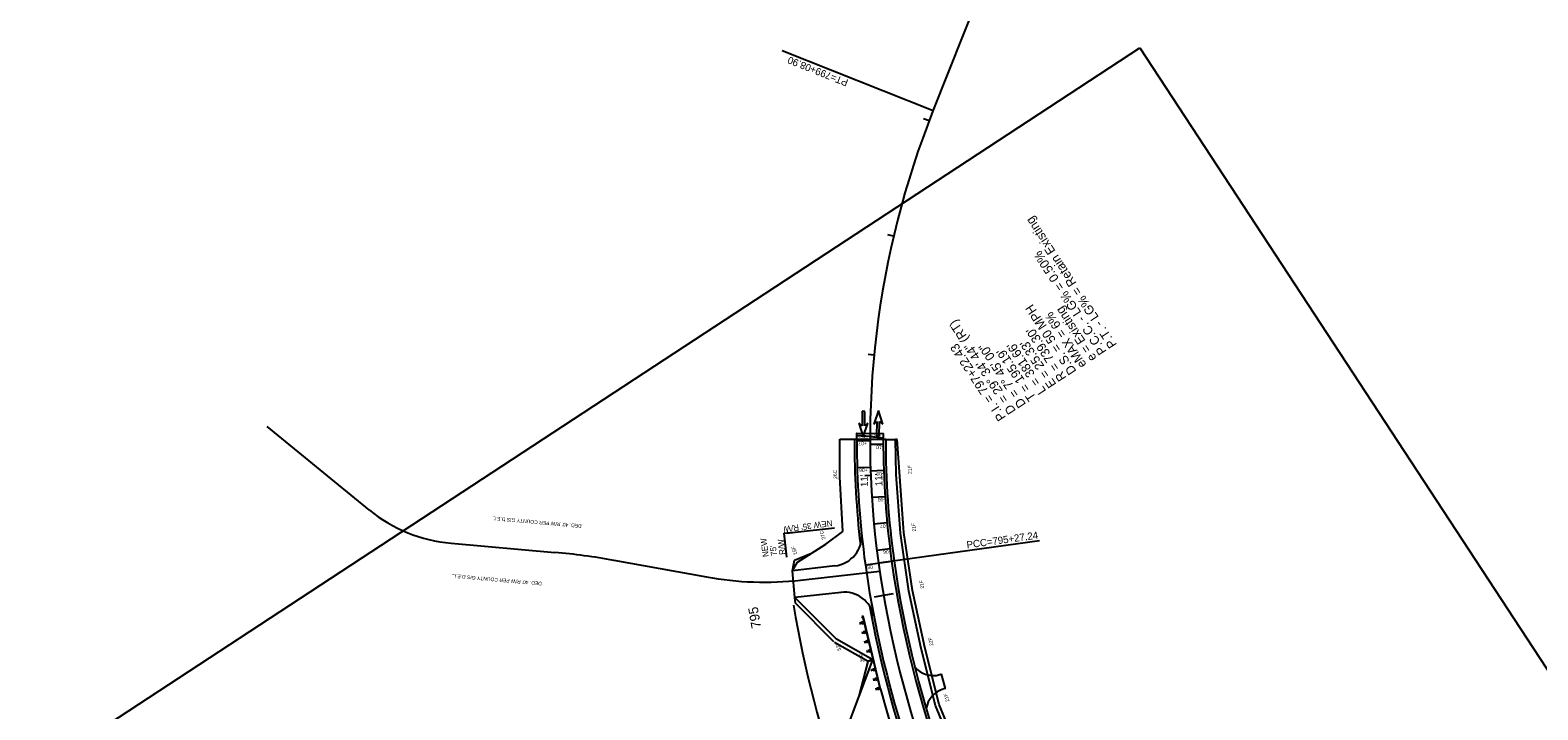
# Model space of a CAD drawing. Extents: x 1551641 to 1624343, y 1119533 to 1136600.
# Drawn here: x 1551641 to 1552891, y 1134769 to 1135333 of the extents above; entities that cross this region are included whole.
import ezdxf

# ---------------------------------------------------------------- set-up
doc = ezdxf.new("R2010")
doc.units = 0
for name, color, linetype in [('Prop CMT Pvmt Surface', 7, 'Continuous'), ('Prop CMT Pvmt Wedge Surface 1', 7, 'Continuous'), ('RD_HC_Cl', 7, 'Continuous'), ('RD_HC_Data', 7, 'Continuous'), ('RD_HC_Data_Tic', 7, 'Continuous'), ('RD_HC_TX_Sta50', 7, 'Continuous'), ('RD_PD_CstnLmt_TX', 7, 'Continuous'), ('RD_Sketch1', 7, 'Continuous'), ('RD_TX_Pipe_ElevEX', 7, 'Continuous'), ('RD_XS_Base', 7, 'Continuous'), ('RD_XS_EarthShd', 7, 'Continuous'), ('RD_XS_ExPaveRet', 7, 'Continuous'), ('RD_XS_Pave', 7, 'Continuous'), ('RD_XS_PaveOvlay', 7, 'Continuous'), ('RD_XS_PaveShd', 7, 'Continuous'), ('RD_XS_TX_Elev_EX', 7, 'Continuous'), ('RD_XS_TX_Slope', 7, 'Continuous'), ('Scratch_Level_0', 7, 'Continuous')]:
    doc.layers.add(name, color=color, linetype=linetype)

msp = doc.modelspace()

# ---------------------------------------------------------------- linework, layer by layer
at = {"layer": 'Prop CMT Pvmt Surface'}
for p, q in [((1552326, 1134992.4), (1552337, 1134992.4)), ((1552337, 1134989.4), (1552348, 1134989.5)), ((1552326.4, 1134970.1), (1552337.4, 1134970.4)), ((1552337.5, 1134967.5), (1552348.5, 1134967.8)), ((1552338.6, 1134945.5), (1552349.5, 1134946.2)), ((1552340.3, 1134923.5), (1552351.2, 1134924.6)), ((1552342.7, 1134901.7), (1552353.6, 1134903)), ((1552333.2, 1134889.5), (1552355, 1134892.5))]:
    msp.add_line(p, q, dxfattribs=at)
at = {"layer": 'Prop CMT Pvmt Wedge Surface 1'}
for p, q in [((1551640.7, 1134715.1), (1552560.8, 1135318)), ((1552560.8, 1135318), (1553547.3, 1133812.4))]:
    msp.add_line(p, q, dxfattribs=at)
at = {"layer": 'RD_HC_Cl'}
for p, q in [((1552389.3, 1135265.7), (1552583.4, 1135754.6)), ((1551836.8, 1135004), (1551921.8, 1134934.9)), ((1551989.6, 1134907.4), (1552075.6, 1134899.8)), ((1552124.5, 1134893.2), (1552201.5, 1134879.4)), ((1552279.4, 1134876.7), (1552345.1, 1134884.1))]:
    msp.add_line(p, q, dxfattribs=at)
for centre, radius, start, end in [((1553076.3, 1134992.8), 739.3, 158.3369, 187.9158), ((1552000.7, 1135031.9), 125, 230.9163, 264.9331), ((1552027, 1134351.9), 550, 79.7884, 84.9331), ((1552249.4, 1135145.1), 270, 259.7884, 276.3798)]:
    msp.add_arc(centre, radius, start, end, dxfattribs=at)
at = {"layer": 'RD_HC_Data'}
for p, q in [((1552389.3, 1135265.7), (1552264.1, 1135315.5)), ((1552344.1, 1134891), (1552477.5, 1134909.6))]:
    msp.add_line(p, q, dxfattribs=at)
at = {"layer": 'RD_HC_Data_Tic'}
for p, q in [((1552386, 1135257.4), (1552381.3, 1135259.2)), ((1552356.6, 1135161.9), (1552351.8, 1135163.1)), ((1552340.4, 1135063.3), (1552335.4, 1135063.8)), ((1552337.6, 1134963.5), (1552332.6, 1134963.3)), ((1552348.3, 1134864.1), (1552340.4, 1134862.7)), ((1552356.2, 1134865.5), (1552348.3, 1134864.1))]:
    msp.add_line(p, q, dxfattribs=at)
at = {"layer": 'RD_Sketch1'}
for p, q in [((1552324, 1134993.5), (1552326, 1134993.5)), ((1552350, 1134993.4), (1552348, 1134993.4))]:
    msp.add_line(p, q, dxfattribs=at)
for centre, radius, start, end in [((1553076.3, 1134992.8), 752.3, 179.952, 186.6169), ((1553076.3, 1134992.8), 726.3, 179.952, 187.9158), ((1553169.1, 1135005.7), 820, 187.9158, 213.2337), ((1553169.1, 1135005.7), 846, 190.2195, 209.0605)]:
    msp.add_arc(centre, radius, start, end, dxfattribs=at)
at = {"layer": 'RD_TX_Pipe_ElevEX'}
for q in [(1552326, 1134996.7), (1552348, 1134994.8)]:
    msp.add_line((1552337, 1134995.9), q, dxfattribs=at)
msp.add_lwpolyline([(1552326, 1134993.5), (1552326, 1134998.5), (1552348, 1134998.4), (1552348, 1134993.4)], close=True, dxfattribs=at)
msp.add_lwpolyline([(1552326, 1134996.7), (1552329.6, 1134996.4), (1552336.1, 1134996), (1552336.6, 1134996), (1552348, 1134994.8)], dxfattribs=at)
at = {"layer": 'RD_XS_Base'}
for p, q in [((1552331.3, 1134846.8), (1552330.3, 1134846.5)), ((1552330.3, 1134846.5), (1552330.5, 1134845.6)), ((1552345.8, 1134786.5), (1552331.3, 1134846.8)), ((1552328.6, 1134841.8), (1552329, 1134840.1)), ((1552330.1, 1134841.2), (1552328.8, 1134840.9)), ((1552329.9, 1134842.1), (1552331.8, 1134842.5)), ((1552330.3, 1134840.4), (1552329.9, 1134842.1)), ((1552332.2, 1134840.8), (1552330.3, 1134840.4)), ((1552330.5, 1134845.6), (1552331, 1134845.7)), ((1552330.5, 1134834), (1552330.9, 1134832.3)), ((1552331.9, 1134833.4), (1552330.7, 1134833.1)), ((1552331, 1134845.7), (1552345.3, 1134786.4)), ((1552331.7, 1134834.3), (1552333.7, 1134834.8)), ((1552332.1, 1134832.6), (1552331.7, 1134834.3)), ((1552331.8, 1134842.5), (1552332.2, 1134840.8)), ((1552333.7, 1134834.8), (1552334.1, 1134833.1)), ((1552334.1, 1134833.1), (1552332.1, 1134832.6)), ((1552332.4, 1134826.2), (1552332.8, 1134824.5)), ((1552333.8, 1134825.7), (1552332.6, 1134825.4)), ((1552333.6, 1134826.5), (1552335.5, 1134827)), ((1552334, 1134824.8), (1552333.6, 1134826.5)), ((1552336, 1134825.3), (1552334, 1134824.8)), ((1552335.5, 1134827), (1552336, 1134825.3)), ((1552334.3, 1134818.4), (1552334.7, 1134816.7)), ((1552335.7, 1134817.9), (1552334.5, 1134817.6)), ((1552335.5, 1134818.7), (1552337.4, 1134819.2)), ((1552335.9, 1134817), (1552335.5, 1134818.7)), ((1552337.8, 1134817.5), (1552335.9, 1134817)), ((1552336.1, 1134810.7), (1552336.6, 1134809)), ((1552337.6, 1134810.1), (1552336.3, 1134809.8)), ((1552337.4, 1134819.2), (1552337.8, 1134817.5)), ((1552337.4, 1134811), (1552339.3, 1134811.4)), ((1552337.8, 1134809.3), (1552337.4, 1134811)), ((1552339.7, 1134809.7), (1552337.8, 1134809.3)), ((1552339.3, 1134811.4), (1552339.7, 1134809.7)), ((1552338, 1134802.9), (1552338.4, 1134801.2)), ((1552339.4, 1134802.3), (1552338.2, 1134802)), ((1552339.2, 1134803.2), (1552341.2, 1134803.6)), ((1552339.6, 1134801.5), (1552339.2, 1134803.2)), ((1552341.6, 1134801.9), (1552339.6, 1134801.5)), ((1552341.2, 1134803.6), (1552341.6, 1134801.9)), ((1552339.9, 1134795.1), (1552340.3, 1134793.4)), ((1552341.3, 1134794.5), (1552340.1, 1134794.3)), ((1552341.1, 1134795.4), (1552343.1, 1134795.9)), ((1552341.5, 1134793.7), (1552341.1, 1134795.4)), ((1552343.5, 1134794.2), (1552341.5, 1134793.7)), ((1552341.8, 1134787.3), (1552342.2, 1134785.6)), ((1552343.2, 1134786.8), (1552342, 1134786.5)), ((1552343, 1134787.6), (1552344.9, 1134788.1)), ((1552343.4, 1134785.9), (1552343, 1134787.6)), ((1552343.1, 1134795.9), (1552343.5, 1134794.2)), ((1552345.3, 1134786.4), (1552343.4, 1134785.9)), ((1552344.9, 1134788.1), (1552345.3, 1134786.4)), ((1552345.3, 1134786.4), (1552345.8, 1134786.5))]:
    msp.add_line(p, q, dxfattribs=at)
msp.add_arc((1553169.1, 1135005.7), 852, 194.9094, 208.1262, dxfattribs=at)
at = {"layer": 'RD_XS_EarthShd'}
msp.add_line((1552326, 1134993.5), (1552348, 1134993.4), dxfattribs=at)
for centre, radius, start, end in [((1553076.3, 1134992.8), 750.3, 179.952, 187.9158), ((1553076.3, 1134992.8), 728.3, 179.952, 187.9158), ((1553169.1, 1135005.7), 844, 187.9158, 213.2337), ((1553169.1, 1135005.7), 822, 187.9158, 213.2337)]:
    msp.add_arc(centre, radius, start, end, dxfattribs=at)
at = {"layer": 'RD_XS_ExPaveRet'}
for p, q in [((1552359.5, 1134993.4), (1552358, 1134993.4)), ((1552365.1, 1134916.2), (1552359.5, 1134993.4)), ((1552372.1, 1134868.2), (1552365.1, 1134916.2)), ((1552274.3, 1134893.2), (1552288.6, 1134899.2)), ((1552272.8, 1134884.6), (1552274.3, 1134893.2)), ((1552275.2, 1134857.7), (1552274.8, 1134862.4)), ((1552382.4, 1134820.8), (1552372.1, 1134868.2)), ((1552307, 1134825.7), (1552275.2, 1134857.7)), ((1552335.5, 1134809.3), (1552307.6, 1134825.2)), ((1552327.9, 1134780.6), (1552335.5, 1134809.3)), ((1552394.2, 1134773.8), (1552382.4, 1134820.8)), ((1552412.8, 1134729), (1552394.2, 1134773.8))]:
    msp.add_line(p, q, dxfattribs=at)
at = {"layer": 'RD_XS_Pave'}
msp.add_line((1552274.9, 1134916.5), (1552307.5, 1134920.1), dxfattribs=at)
for centre, radius, start, end in [((1552249.4, 1135145.1), 230, 274.0673, 276.3798), ((1553076.3, 1134992.8), 814.3, 185.4382, 186.8463), ((1553169.1, 1135005.7), 908, 189.4862, 209.8315)]:
    msp.add_arc(centre, radius, start, end, dxfattribs=at)
at = {"layer": 'RD_XS_PaveOvlay'}
for p, q in [((1552330.6, 1135016.8), (1552330.4, 1135004.8)), ((1552332.8, 1135016.7), (1552330.6, 1135016.8)), ((1552332.6, 1135004.7), (1552332.8, 1135016.7)), ((1552344, 1135017.4), (1552340.1, 1135006.2)), ((1552347.5, 1135006), (1552344, 1135017.4)), ((1552327.8, 1135006.9), (1552331.3, 1134995.6)), ((1552330.4, 1135004.8), (1552327.8, 1135006.9)), ((1552331.3, 1134995.6), (1552335.2, 1135006.8)), ((1552335.2, 1135006.8), (1552332.6, 1135004.7)), ((1552340.1, 1135006.2), (1552342.7, 1135008.2)), ((1552342.7, 1135008.2), (1552342.5, 1134996.2)), ((1552342.5, 1134996.2), (1552344.7, 1134996.2)), ((1552344.7, 1134996.2), (1552344.9, 1135008.2)), ((1552344.9, 1135008.2), (1552347.5, 1135006))]:
    msp.add_line(p, q, dxfattribs=at)
at = {"layer": 'RD_XS_PaveShd'}
for p, q in [((1552307.9, 1134888.5), (1552272.8, 1134884.6)), ((1552274.8, 1134862.4), (1552272.8, 1134884.6)), ((1552313, 1134866.6), (1552274.8, 1134862.4)), ((1552396.2, 1134798.8), (1552394.8, 1134798.4)), ((1552399.6, 1134787), (1552396.2, 1134798.8)), ((1552399.6, 1134787), (1552398.1, 1134786.6))]:
    msp.add_line(p, q, dxfattribs=at)
for centre, radius, start, end in [((1552305.1, 1134913.4), 25, 276.3798, 5.8818), ((1552315.7, 1134841.8), 25, 10.8742, 96.3798), ((1552389.5, 1134817.7), 20, 219.7135, 285.4264), ((1552403.4, 1134767.3), 20, 105.4264, 171.1406)]:
    msp.add_arc(centre, radius, start, end, dxfattribs=at)
at = {"layer": 'RD_XS_TX_Elev_EX'}
for p, q in [((1552311.9, 1134962.4), (1552312, 1134993.5)), ((1552312, 1134993.5), (1552324, 1134993.5)), ((1552350, 1134993.4), (1552358, 1134993.4)), ((1552358.6, 1134964.3), (1552358, 1134993.4)), ((1552314.5, 1134917.2), (1552311.9, 1134962.4)), ((1552362.2, 1134915.8), (1552358.6, 1134964.3)), ((1552300.3, 1134906.7), (1552314.5, 1134917.2)), ((1552369.1, 1134867.7), (1552362.2, 1134915.8)), ((1552276.9, 1134891.7), (1552300.3, 1134906.7)), ((1552272.8, 1134884.6), (1552276.9, 1134891.7)), ((1552309.1, 1134827.8), (1552274.8, 1134862.4)), ((1552379.5, 1134820.1), (1552369.1, 1134867.7)), ((1552339.2, 1134810.6), (1552309.1, 1134827.8)), ((1552316.7, 1134750.5), (1552339.2, 1134810.6)), ((1552391.4, 1134772.9), (1552379.5, 1134820.1)), ((1552410, 1134727.8), (1552391.4, 1134772.9))]:
    msp.add_line(p, q, dxfattribs=at)
at = {"layer": 'Scratch_Level_0'}
msp.add_arc((1553169.1, 1135005.7), 833, 187.9158, 213.2337, dxfattribs=at)

# ---------------------------------------------------------------- texts
at = {"layer": 'Prop CMT Pvmt Surface'}
for s, rotation, p in [('+07', 179.952, (1552334.3, 1134991.6)), ('-10', 182.257, (1552347.9, 1134988.6)), ('+06', 179.952, (1552335, 1134969.4)), ('-09', 182.257, (1552348.1, 1134966.5)), ('-08', 182.257, (1552349.4, 1134945.1)), ('-07', 182.257, (1552351.2, 1134923.2)), ('-06', 182.257, (1552353.8, 1134901.7)), ('06', 182.257, (1552339.3, 1134889.2))]:
    msp.add_text(s, height=3, rotation=rotation, dxfattribs=at).set_placement(p)
at = {"layer": 'RD_HC_Data'}
for s, height, rotation, p in [('PT=799+08.90', 6, 158.3369, (1552319.5, 1135291.5)), ('P.T. - LG% = Retain Existing', 7.5, 123.2337, (1552541.9, 1135072)), ('P.C.C. - LG% = 0.50%', 7.5, 123.2337, (1552533.5, 1135066.5)), ('D.S. = 50 MPH', 7.5, 123.2337, (1552508.4, 1135050)), ('eMAX = 6%', 7.5, 123.2337, (1552516.8, 1135055.5)), ('e = Existing', 7.5, 123.2337, (1552525.2, 1135061)), ('    = 29%%d 34\' 44" (RT)', 7.5, 123.2337, (1552458.2, 1135017.2)), ("R = 739.30'", 7.5, 123.2337, (1552500.1, 1135044.6)), ('P.I. = 797+22.43', 7.5, 123.2337, (1552449.9, 1135011.7)), ('D = 7%%d 45\' 00"', 7.5, 123.2337, (1552466.6, 1135022.6)), ("L = 381.66'", 7.5, 123.2337, (1552483.3, 1135033.6)), ("E = 25.33'", 7.5, 123.2337, (1552491.7, 1135039.1)), ("T = 195.19'", 7.5, 123.2337, (1552475, 1135028.1)), ('D', 7.5, 123.2337, (1552458.2, 1135017.2)), ('PCC=795+27.24', 6, 7.9158, (1552417.5, 1134903))]:
    msp.add_text(s, height=height, rotation=rotation, dxfattribs=at).set_placement(p)
at = {"layer": 'RD_HC_TX_Sta50'}
msp.add_text('795', height=8, rotation=99.7998, dxfattribs=at).set_placement((1552246.8, 1134837.6))
at = {"layer": 'RD_PD_CstnLmt_TX'}
for rotation, p in [(174.9645, (1552098, 1134923)), (174.9681, (1552065, 1134875.3))]:
    msp.add_text("DED. 40' R/W PER COUNTY GIS D.E.L.", height=3, rotation=rotation, dxfattribs=at).set_placement(p)
at = {"layer": 'RD_TX_Pipe_ElevEX'}
for s, p in [('-10.1636', (1552338.4, 1134996.1)), ('+7.0455', (1552327.6, 1134994.3))]:
    msp.add_text(s, height=1.5, rotation=359.952, dxfattribs=at).set_placement(p)
at = {"layer": 'RD_XS_Pave'}
for s, rotation, p in [("NEW 35' R/W", 187.4469, (1552305.5, 1134926.6)), ('NEW ', 97.4469, (1552253.1, 1134896.3)), ('R/W', 97.4469, (1552267, 1134898.1)), ("75' ", 97.4469, (1552260, 1134897.2))]:
    msp.add_text(s, height=5, rotation=rotation, dxfattribs=at).set_placement(p)
at = {"layer": 'RD_XS_PaveOvlay'}
for p in [(1552335.4, 1134954.1), (1552347.4, 1134954.8)]:
    msp.add_text("11'", height=6, rotation=92.0205, dxfattribs=at).set_placement(p)
at = {"layer": 'RD_XS_TX_Slope'}
for s, rotation, p in [('21F', 92.277, (1552371.6, 1134964.8)), ('26C', 92.277, (1552309.8, 1134960.7)), ('21F', 96.152, (1552375.1, 1134917.2)), ('27C', 107.1106, (1552300.2, 1134910.9)), ('15F', 106.9184, (1552276.7, 1134898.3)), ('21F', 99.7895, (1552381.9, 1134869.9)), ('52F', 107.1106, (1552313.1, 1134818.7)), ('22F', 103.2286, (1552389.6, 1134822.6)), ('20F', 103.2286, (1552332.4, 1134809)), ('21F', 106.6677, (1552402.9, 1134776.3))]:
    msp.add_text(s, height=3, rotation=rotation, dxfattribs=at).set_placement(p)

doc.saveas('drawing.dxf')
